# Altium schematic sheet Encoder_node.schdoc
size 292 x 205 mm; Device: A_A4; Symbol: A_A4; Name: A_A4; Designator: A; @Project Name: Sheet_1; REV: 1.0; Date: 2026-01-13; Sheet: 1/1; Draw By: ocp21; Company: Your Company; Manufacturer Part: ?; Convert to PCB: yes; Add into BOM: yes; Origin Footprint: NONE; Unique ID: frame_lib_1
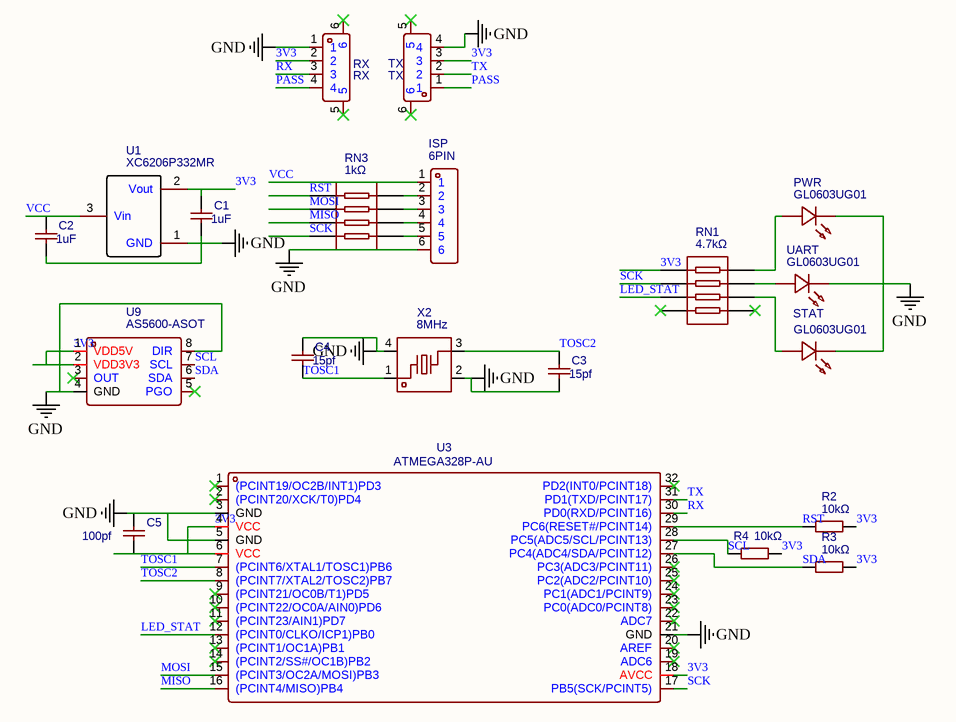
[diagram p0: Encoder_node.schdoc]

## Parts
C1  1uF  [C0402]
C2  1uF  [C0402]
C3  15pf  [C0402]
C4  15pf  [C0402]
C5  100pf  [C0402]
ISP  6PIN  [HDR-TH_6P-P1.27-V-M]
PWR  GL0603UG01  [LED0603-RD]
R2  10kΩ  [R0603]
R3  10kΩ  [R0603]
R4  10kΩ  [R0603]
RN1  4.7kΩ  [RES-ARRAY-SMD_0603-8P-L3.2-W1.6-BL]
RN3  1kΩ  [RES-ARRAY-SMD_0603-8P-L3.2-W1.6-BL]
RX  RX  [CONN-SMD_4P-P1.50_ZX-ZH1.5-4PWT]
STAT  GL0603UG01  [LED0603-RD]
TX  TX  [CONN-SMD_4P-P1.50_ZX-ZH1.5-4PWT]
U1  XC6206P332MR  [SOT-23-3_L2.9-W1.6-P1.90-LS2.8-BR]
U3  ATMEGA328P-AU  [TQFP-32_L7.0-W7.0-P0.80-LS9.0-BL]
U9  AS5600-ASOT  [SOIC-8_L5.0-W4.0-P1.27-LS6.0-BL]
UART  GL0603UG01  [LED0603-RD]
X2  8MHz  [CRYSTAL-SMD_4P-L3.2-W2.5-BL]

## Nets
GND: C1.1 C2.1 C3.1 C4.2 C5.2 ISP.6 PWR.1(K) RX.1 STAT.1(K) TX.4 U1.1(GND) U3.3(GND) U3.5(GND) U3.21(GND) U9.4(GND) U9.8(DIR) UART.1(K) X2.2(GND) X2.4(GND)
3V3: C1.2 C5.1 R2.2 R3.2 R4.2 RN1.1 RX.2 TX.3 U1.2(Vout) U3.4(VCC) U3.6(VCC) U3.18(AVCC) U9.1(VDD5V) U9.2(VDD3V3)
LED_STAT: RN1.3 U3.12((PCINT0/CLKO/ICP1)PB0)
MISO: RN3.3 U3.16((PCINT4/MISO)PB4)
MOSI: RN3.2 U3.15((PCINT3/OC2A/MOSI)PB3)
PASS: RX.4 TX.1
RST: R2.1 RN3.1 U3.29(PC6(RESET#/PCINT14))
RX: RX.3 U3.30(PD0(RXD/PCINT16))
SCK: RN1.2 RN3.4 U3.17(PB5(SCK/PCINT5))
SCL: R4.1 U3.28(PC5(ADC5/SCL/PCINT13)) U9.7(SCL)
SDA: R3.1 U3.27(PC4(ADC4/SDA/PCINT12)) U9.6(SDA)
TOSC1: C4.1 U3.7((PCINT6/XTAL1/TOSC1)PB6) X2.1
TOSC2: C3.2 U3.8((PCINT7/XTAL2/TOSC2)PB7) X2.3
TX: TX.2 U3.31(PD1(TXD/PCINT17))
VCC: C2.2 ISP.1 U1.3(Vin)
NetISP_2: ISP.2 RN3.8
NetISP_3: ISP.3 RN3.7
NetISP_4: ISP.4 RN3.6
NetISP_5: ISP.5 RN3.5
NetPWR_2: PWR.2(A) RN1.8
NetRN1_6: RN1.6 STAT.2(A)
NetRN1_7: RN1.7 UART.2(A)

Not connected (* = marked no-connect by the designer): RN1 4* 5*; RX 5* 6*; TX 5* 6*; U3 1((PCINT19/OC2B/INT1)PD3)* 2((PCINT20/XCK/T0)PD4)* 9((PCINT21/OC0B/T1)PD5)* 10((PCINT22/OC0A/AIN0)PD6)* 11((PCINT23/AIN1)PD7)* 13((PCINT1/OC1A)PB1)* 14((PCINT2/SS#/OC1B)PB2)* 19(ADC6)* 20(AREF)* 22(ADC7)* 23(PC0(ADC0/PCINT8))* 24(PC1(ADC1/PCINT9))* 25(PC2(ADC2/PCINT10))* 26(PC3(ADC3/PCINT11))* 32(PD2(INT0/PCINT18))*; U9 3(OUT)* 5(PGO)*

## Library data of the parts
C1 = CL05A105KP5NNNC: Manufacturer: SAMSUNG(三星); Convert to PCB: yes; UniqueId: gge463442e19da02213; ModelId: 32fe2cf9314f444ca2785a33c2db7189; ModelName: C0402_L1.0-W0.5-H0.5; ModelTransform: v2:[39.37007874015748,0,0,0,39.37007874015748,0,0,0,39.37007874015748,0.001,0.001,0]
C2 = CL05A105KP5NNNC: Manufacturer: SAMSUNG(三星); Convert to PCB: yes; UniqueId: gge7c9095b5e9efb690; ModelId: 32fe2cf9314f444ca2785a33c2db7189; ModelName: C0402_L1.0-W0.5-H0.5; ModelTransform: v2:[39.37007874015748,0,0,0,39.37007874015748,0,0,0,39.37007874015748,0.001,0.001,0]
C3 = CL05A105KP5NNNC: Manufacturer: SAMSUNG(三星); Convert to PCB: yes; UniqueId: gge20398a884c195f1b; ModelId: 32fe2cf9314f444ca2785a33c2db7189; ModelName: C0402_L1.0-W0.5-H0.5; ModelTransform: v2:[39.37007874015748,0,0,0,39.37007874015748,0,0,0,39.37007874015748,0.001,0.001,0]
C4 = CL05A105KP5NNNC: Manufacturer: SAMSUNG(三星); Convert to PCB: yes; UniqueId: ggefab90927b80e47a4; ModelId: 32fe2cf9314f444ca2785a33c2db7189; ModelName: C0402_L1.0-W0.5-H0.5; ModelTransform: v2:[39.37007874015748,0,0,0,39.37007874015748,0,0,0,39.37007874015748,0.001,0.001,0]
C5 = CL05A105KP5NNNC: Manufacturer: SAMSUNG(三星); Convert to PCB: yes; UniqueId: gge2ba651aee9152ccb; ModelId: 32fe2cf9314f444ca2785a33c2db7189; ModelName: C0402_L1.0-W0.5-H0.5; ModelTransform: v2:[39.37007874015748,0,0,0,39.37007874015748,0,0,0,39.37007874015748,0.001,0.001,0]
ISP = PZ127V-11-06-H25: Manufacturer: XFCN(兴飞); Convert to PCB: yes; UniqueId: gge08f31e13f1fd5ad6; ModelId: 91a400a27efe4f9bb82f5bf66d80642e; ModelTransform: v2:[39.37007874015748,0,0,0,39.37007874015748,0,0,0,39.37007874015748,0.001,0.001,-118.11]
PWR = GL0603UG01: Manufacturer: Guiguang light(桂光光电); Convert to PCB: yes; UniqueId: gged3093af8e8325be6; ModelId: 3c2caa1a3e7d4a5a87f46b87d898ef41; ModelTransform: v2:[39.37007874015748,0,0,0,39.37007874015748,0,0,0,39.37007874015748,0.001,-0.001,0]
R2 = 0603WAF1002T5E: Manufacturer: UNI-ROYAL(厚声); Convert to PCB: yes; UniqueId: ggeaa9539d2d731f168; ModelId: 6bd5cd867e9542ebae21caaf5d2d4c4d; ModelTransform: v2:[2.410722045565656e-15,39.37007874015748,0,-39.37007874015748,2.410722045565656e-15,0,0,0,39.37007874015748,0.002,0.001,0]
R3 = 0603WAF1002T5E: Manufacturer: UNI-ROYAL(厚声); Convert to PCB: yes; UniqueId: gged2b0cb9eddcc8f8b; ModelId: 6bd5cd867e9542ebae21caaf5d2d4c4d; ModelTransform: v2:[2.410722045565656e-15,39.37007874015748,0,-39.37007874015748,2.410722045565656e-15,0,0,0,39.37007874015748,0.002,0.001,0]
R4 = 0603WAF1002T5E: Manufacturer: UNI-ROYAL(厚声); Convert to PCB: yes; UniqueId: ggef4926452c1d26292; ModelId: 6bd5cd867e9542ebae21caaf5d2d4c4d; ModelTransform: v2:[2.410722045565656e-15,39.37007874015748,0,-39.37007874015748,2.410722045565656e-15,0,0,0,39.37007874015748,0.002,0.001,0]
RN1 = 4D03WGJ0472T5E: Manufacturer: UNI-ROYAL(厚声); Convert to PCB: yes; UniqueId: ggef91e798257f1cc52; ModelId: 551b3dd0a237409fa823f51b33d3f6d1; ModelName: R0603-8P_L3.2-W1.6-H0.6; ModelTransform: v2:[39.37007874015748,0,0,0,39.37007874015748,0,0,0,39.37007874015748,0.001,-0.001,0]
RN3 = 4D03WGJ0102T5E: Manufacturer: UNI-ROYAL(厚声); Convert to PCB: yes; UniqueId: gge8cb3440d5222c71d; ModelId: 551b3dd0a237409fa823f51b33d3f6d1; ModelName: R0603-8P_L3.2-W1.6-H0.6; ModelTransform: v2:[39.37007874015748,0,0,0,39.37007874015748,0,0,0,39.37007874015748,0.001,-0.001,0]
RX = ZX-ZH1.5-4PWT: Manufacturer: Megastar(兆星); Convert to PCB: yes; UniqueId: gge99a73c97da5aac1c; ModelId: 919a32195fe24ac4bff0cbe012986613; ModelTransform: v2:[39.37007874015748,0,0,0,39.37007874015748,0,0,0,39.37007874015748,-0.002,-26.024,0]
STAT = GL0603UG01: Manufacturer: Guiguang light(桂光光电); Convert to PCB: yes; UniqueId: gge8c8eeec15dbb3182; ModelId: 3c2caa1a3e7d4a5a87f46b87d898ef41; ModelTransform: v2:[39.37007874015748,0,0,0,39.37007874015748,0,0,0,39.37007874015748,0.001,-0.001,0]
TX = ZX-ZH1.5-4PWT: Manufacturer: Megastar(兆星); Convert to PCB: yes; UniqueId: gge7bba95b7947b6b8d; ModelId: 919a32195fe24ac4bff0cbe012986613; ModelTransform: v2:[39.37007874015748,0,0,0,39.37007874015748,0,0,0,39.37007874015748,-0.002,-26.024,0]
U1 = XC6206P332MR-G: Manufacturer: TOREX(特瑞仕); Convert to PCB: yes; UniqueId: gge8626a56430a94118; ModelId: cefd4596db214da394d9632b2b88f8f2; ModelName: SOT-23-3L_L2.9-W1.6-H1.1-LS2.8-P0.95; ModelTransform: v2:[2.410722045565656e-15,39.37007874015748,0,-39.37007874015748,2.410722045565656e-15,0,0,0,39.37007874015748,0,-0.001,0]
U3 = ATMEGA328P-AU: Manufacturer: MICROCHIP(美国微芯); Convert to PCB: yes; UniqueId: gge3aafcb9c48049203; ModelId: 4d9f6c3430024506b87ce44b53201fc5; ModelName: TQFP-32_L7.0-W7.0-H1.2-LS9.0-P0.80; ModelTransform: v2:[2.410722045565656e-15,39.37007874015748,0,-39.37007874015748,2.410722045565656e-15,0,0,0,39.37007874015748,-0.04,0.079,0]
U9 = AS5600-ASOT: Manufacturer: ams(艾迈斯半导体); Convert to PCB: yes; UniqueId: gge5f9116216eb103d2; ModelId: 7abc64c95a1a4a04a4ef38f9097c870b; ModelTransform: v2:[39.37007874015748,0,0,0,39.37007874015748,0,0,0,39.37007874015748,-0.001,0,0]
UART = GL0603UG01: Manufacturer: Guiguang light(桂光光电); Convert to PCB: yes; UniqueId: gge604c63b080174abb; ModelId: 3c2caa1a3e7d4a5a87f46b87d898ef41; ModelTransform: v2:[39.37007874015748,0,0,0,39.37007874015748,0,0,0,39.37007874015748,0.001,-0.001,0]
X2 = X32258MOB4SI: Manufacturer: YXC(扬兴晶振); Convert to PCB: yes; UniqueId: gged9acb6b6c49e108c; ModelId: 02485e56ba8d4732a26526d2983fc729; ModelTransform: v2:[39.37007874015748,0,0,0,39.37007874015748,0,0,0,39.37007874015748,-0.001,0,0]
